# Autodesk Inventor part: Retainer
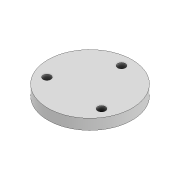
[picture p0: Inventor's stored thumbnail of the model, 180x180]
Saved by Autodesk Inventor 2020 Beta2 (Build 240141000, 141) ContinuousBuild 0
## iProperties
Created: 2019-03
Part Number: Retainer
Material: Generic
Document SubType Name: Modeling
Designer: LENOVO-CADCIM
Density: 1 g/cm^3
Appearance: Default
Author: LENOVO-CADCIM
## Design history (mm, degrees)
sketch "Sketch1" dims "d1" = 150
  geometry: C1 r 100 at (0, 0); 3 further points
  constraints: 2 coincident, 1 centre point, 1 vertical alignment, 2 other
  dimensions: "d0" = 200 diameter of C1
extrude "Extrusion1" new body sketch "Sketch1" stored distance "d2" = 25; taper "d3" = 0 deg
sketch "Sketch2" dims "d4" = 150
  geometry: 3 further points
  constraints: 1 coincident, 1 vertical alignment, 2 other
hole "Hole1" sketch "Sketch2" at (0, 75) diameter "d5" = 18.376; stored, may be unused: countersink angle "d9" = 90 deg, drill point angle "d11" = 118 deg; dims "d6" = 40, "d7" = 4.4, "d8" = 2, "d10" = 47.3
pattern_circular "Circular Pattern1" dims angle "d13" = 360 deg
body "Solid1"
